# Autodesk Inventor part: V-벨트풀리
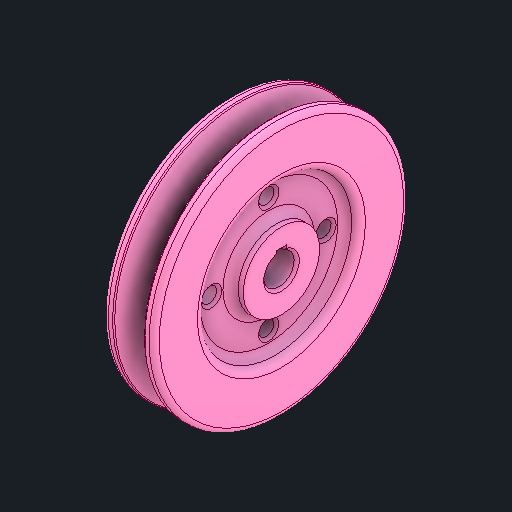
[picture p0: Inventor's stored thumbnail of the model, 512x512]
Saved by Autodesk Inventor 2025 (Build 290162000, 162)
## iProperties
Created: 2025-08
Part Number: V-벨트풀리
Material: 강철, 연강
Document SubType Name: Modeling
Designer: infra15
Density: 7.86 g/cm^3
Appearance: 기본값
Author: jhkim
Sending System: Autodesk Inventor 2026
Preprocessor: ST-DEVELOPER v20.1
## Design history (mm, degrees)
feature "솔리드1"
node "솔리드2"
